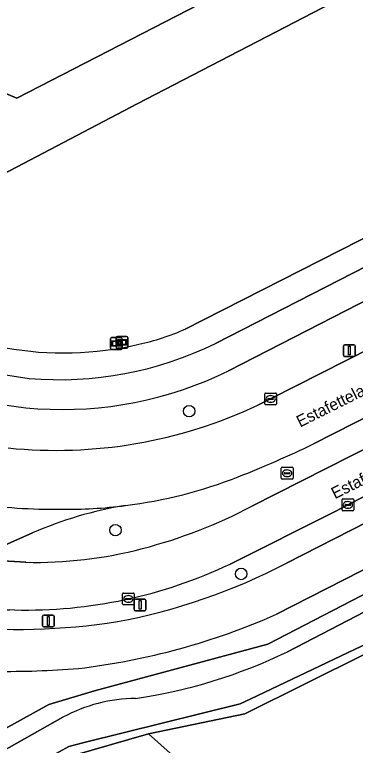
# Model space of a CAD drawing. Extents: x 158835 to 160077, y 386387 to 387778.
# Drawn here: x 159364.2 to 159393.2, y 386924.8 to 386987.1 of the extents above; entities that cross this region are included whole.
import ezdxf

# ---------------------------------------------------------------- set-up
doc = ezdxf.new("R2010")
doc.units = 0
for name, color, linetype in [('IMGEO_Berm_groen', 7, 'Continuous'), ('IMGEO_Boom', 7, 'Continuous'), ('IMGEO_Fietspad_gesloten', 7, 'Continuous'), ('IMGEO_Groenvoorziening', 7, 'Continuous'), ('IMGEO_Hek', 7, 'Continuous'), ('IMGEO_Kolk', 7, 'Continuous'), ('IMGEO_Lichtmast', 7, 'Continuous'), ('IMGEO_Loofbos', 7, 'Continuous'), ('IMGEO_Oever', 7, 'Continuous'), ('IMGEO_Openbare_ruimte_label', 7, 'Continuous'), ('IMGEO_OVBaan_gesloten', 7, 'Continuous'), ('IMGEO_Rijbaan_lokaal_gesloten', 7, 'Continuous'), ('IMGEO_Rioolput', 7, 'Continuous'), ('IMGEO_Verkeersbordpaal', 7, 'Continuous'), ('IMGEO_Verklikker', 7, 'Continuous'), ('IMGEO_Voetpad_open', 7, 'Continuous'), ('IMGEO_Waterloop', 7, 'Continuous')]:
    doc.layers.add(name, color=color, linetype=linetype)

msp = doc.modelspace()

# ---------------------------------------------------------------- linework, layer by layer
at = {"layer": 'IMGEO_Berm_groen'}
for points in [[(159428.091, 386980.187), (159382.431, 386956.783)], [(159384.924, 386953.836), (159386.022, 386954.376), (159398.908, 386960.912), (159415.355, 386969.266), (159429.86, 386976.665)], [(159432.141, 386972.104), (159389.664, 386950.538)], [(159384.418, 386945.227), (159433.268, 386969.982)], [(159434.931, 386966.882), (159434.868, 386966.85), (159404.602, 386951.444), (159392.61, 386945.349), (159391.514, 386944.789), (159382.575, 386940.303)], [(159387.376, 386940.385), (159435.723, 386965.048)], [(159365.727, 386942.951), (159362.552, 386941.571)], [(159362.672, 386940.602), (159365.133, 386940.451)]]:
    msp.add_lwpolyline(points, dxfattribs=at)
for centre, radius, start, end in [((159368.268, 386985.461), 31.985, 236.21061, 296.28288), ((159367.73, 386990.355), 40.364, 264.19141, 295.21233), ((159346.049, 387041.588), 100.958, 291.62283, 295.59561), ((159368.684, 386984.869), 39.889, 277.13541, 291.41905), ((159378.86, 386913.065), 32.645, 99.20291, 113.72196), ((159364.033, 386984.103), 43.897, 284.58939, 297.67073), ((159365.962, 386976.316), 35.874, 268.67508, 284.73992), ((159363.347, 386986.442), 51.949, 280.6721, 297.55231), ((159365.152, 386977.019), 40.64, 268.64408, 295.38662), ((159365.477, 386830.407), 105.991, 90.69551, 94.25258), ((159364.488, 386989.797), 55.062, 263.9691, 278.85816)]:
    msp.add_arc(centre, radius, start, end, dxfattribs=at)
at = {"layer": 'IMGEO_Boom'}
for centre in [(159379.078, 386953.336), (159372.785, 386943.191), (159383.508, 386939.459)]:
    msp.add_circle(centre, 0.489, dxfattribs=at)
at = {"layer": 'IMGEO_Fietspad_gesloten'}
for points in [[(159382.431, 386956.783), (159428.091, 386980.187), (159426.93, 386982.455), (159381.329, 386959.114)], [(159386.519, 386936.025), (159434.012, 386960.244), (159437.242, 386961.891), (159435.723, 386965.048), (159387.376, 386940.385)]]:
    msp.add_lwpolyline(points, dxfattribs=at)
for centre, radius, start, end in [((159369.367, 386988.541), 32.652, 237.26969, 263.08821), ((159368.04, 386986.036), 30.023, 265.02753, 296.27055), ((159368.268, 386985.461), 31.985, 236.21061, 296.28288), ((159363.347, 386986.442), 51.949, 280.6721, 297.55231), ((159362.835, 386989.408), 58.401, 276.67679, 293.92526), ((159364.488, 386989.797), 55.062, 263.9691, 278.85816), ((159363.587, 387005.299), 74.142, 269.19844, 274.6711)]:
    msp.add_arc(centre, radius, start, end, dxfattribs=at)
at = {"layer": 'IMGEO_Groenvoorziening'}
for points in [[(159492.942, 387127.124), (159492.925, 387127.157), (159491.486, 387129.957), (159491.48, 387129.969), (159454.996, 387200.96), (159454.739, 387200.828), (159488.799, 387134.444), (159483.442, 387131.694), (159530.436, 387039.892), (159523.22, 387036.235), (159466.963, 387007.729), (159456.775, 387027.573), (159364.368, 386980.011), (159361.936, 386981.03), (159330.518, 387042.115), (159326.469, 387040.039), (159326.519, 387039.941), (159327.376, 387040.359), (159360.9, 386972.353), (159374.649, 386979.517), (159454.32, 387020.797), (159462.644, 387004.65), (159523.508, 387035.675), (159536.529, 387042.312)], [(159483.442, 387131.694), (159453.236, 387116.189), (159453.617, 387115.493), (159447.106, 387112.128), (159446.642, 387112.841), (159431.844, 387105.183), (159432.221, 387104.371), (159425.755, 387101.094), (159425.292, 387101.79), (159413.519, 387095.807), (159415.826, 387091.297), (159418.055, 387087.12), (159407.481, 387081.56), (159395.596, 387075.514), (159389.288, 387072.22), (159387.317, 387071.247), (159330.518, 387042.115), (159361.936, 386981.03), (159364.368, 386980.011), (159456.775, 387027.573), (159466.963, 387007.729), (159523.22, 387036.235), (159530.436, 387039.892)], [(159426.473, 386939.935), (159425.959, 386940.91), (159436.694, 386946.325), (159437.191, 386945.362), (159454.436, 386954.123), (159458.282, 386956.083), (159457.971, 386956.706), (159457.606, 386957.3), (159457.189, 386957.858), (159456.724, 386958.376), (159456.214, 386958.851), (159455.963, 386959.046), (159444.244, 386952.199), (159437.136, 386954.065), (159414.812, 386942.941), (159383.823, 386927.545), (159375.595, 386925.829), (159379.553, 386922.312), (159383.008, 386919.242), (159383.953, 386918.403), (159408.648, 386930.908), (159408.146, 386931.898), (159418.899, 386937.349), (159419.39, 386936.348)]]:
    msp.add_lwpolyline(points, close=True, dxfattribs=at)
for points in [[(159332.172, 386900.099), (159339.03, 386909.825), (159341.407, 386912.222), (159344.595, 386914.968), (159353.41, 386920.761), (159367.113, 386928.324), (159370.995, 386929.506), (159385.785, 386933.475), (159425.412, 386953.997), (159434.793, 386958.672), (159434.012, 386960.244), (159386.519, 386936.025)], [(159359.061, 386915.103), (159379.553, 386922.312), (159375.595, 386925.829), (159369.094, 386923.958), (159353.377, 386915.342)]]:
    msp.add_lwpolyline(points, dxfattribs=at)
for centre, radius, start, end in [((159362.835, 386989.408), 58.401, 276.67679, 293.92526), ((159363.587, 387005.299), 74.142, 269.19844, 274.6711)]:
    msp.add_arc(centre, radius, start, end, dxfattribs=at)
at = {"layer": 'IMGEO_Hek'}
for points in [[(159374.649, 386979.517), (159454.32, 387020.797), (159462.644, 387004.65)], [(159374.649, 386979.517), (159360.9, 386972.353)]]:
    msp.add_lwpolyline(points, dxfattribs=at)
at = {"layer": 'IMGEO_Kolk'}
for p, q in [((159385.521, 386953.95), (159385.521, 386954.802)), ((159385.596, 386954.876), (159386.448, 386954.876)), ((159386.522, 386954.802), (159386.522, 386953.95)), ((159385.78, 386954.37), (159385.78, 386954.382)), ((159386.218, 386954.333), (159385.82, 386954.333)), ((159385.823, 386954.419), (159386.221, 386954.419)), ((159386.032, 386954.096), (159386.007, 386954.096)), ((159386.009, 386954.656), (159386.034, 386954.656)), ((159386.264, 386954.382), (159386.264, 386954.37)), ((159386.448, 386953.876), (159385.596, 386953.876)), ((159392.11, 386944.922), (159392.11, 386945.774)), ((159392.185, 386945.848), (159393.037, 386945.848)), ((159392.369, 386945.342), (159392.369, 386945.354)), ((159392.412, 386945.391), (159392.81, 386945.391)), ((159392.598, 386945.628), (159392.623, 386945.628)), ((159392.853, 386945.354), (159392.853, 386945.342)), ((159393.111, 386945.774), (159393.111, 386944.922)), ((159393.037, 386944.848), (159392.185, 386944.848)), ((159392.807, 386945.305), (159392.409, 386945.305)), ((159392.621, 386945.068), (159392.596, 386945.068)), ((159373.39, 386936.907), (159373.39, 386937.759)), ((159373.465, 386937.833), (159374.317, 386937.833)), ((159373.649, 386937.327), (159373.649, 386937.339)), ((159374.087, 386937.29), (159373.689, 386937.29)), ((159373.692, 386937.376), (159374.09, 386937.376)), ((159373.878, 386937.613), (159373.903, 386937.613)), ((159374.133, 386937.339), (159374.133, 386937.327)), ((159374.391, 386937.759), (159374.391, 386936.907)), ((159374.317, 386936.833), (159373.465, 386936.833)), ((159373.901, 386937.053), (159373.876, 386937.053))]:
    msp.add_line(p, q, dxfattribs=at)
for points in [[(159385.521, 386953.95), (159385.521, 386954.802)], [(159385.596, 386954.876), (159386.448, 386954.876)], [(159386.522, 386954.802), (159386.522, 386953.95)], [(159386.448, 386953.876), (159385.596, 386953.876)], [(159392.11, 386944.922), (159392.11, 386945.774)], [(159392.185, 386945.848), (159393.037, 386945.848)], [(159393.111, 386945.774), (159393.111, 386944.922)], [(159393.037, 386944.848), (159392.185, 386944.848)], [(159373.39, 386936.907), (159373.39, 386937.759)], [(159373.465, 386937.833), (159374.317, 386937.833)], [(159374.391, 386937.759), (159374.391, 386936.907)], [(159374.317, 386936.833), (159373.465, 386936.833)]]:
    msp.add_lwpolyline(points, dxfattribs=at)
for centre, radius, start, end in [((159385.598, 386954.8), 0.0765, 91.55205, 178.44795), ((159385.598, 386954.8), 0.0765, 91.55205, 178.44795), ((159386.446, 386954.8), 0.0765, 1.55205, 88.44795), ((159386.446, 386954.8), 0.0765, 1.55205, 88.44795), ((159385.82, 386954.379), 0.0403, 85.87752, 175.75265), ((159385.817, 386954.369), 0.0366, 178.93798, 274.71019), ((159386.221, 386954.376), 0.043, 264.86636, 352.45326), ((159386.225, 386954.381), 0.0386, 1.73085, 96.63898), ((159385.598, 386953.952), 0.0765, 181.55205, 268.44795), ((159385.598, 386953.952), 0.0765, 181.55205, 268.44795), ((159386.446, 386953.952), 0.0765, 271.55205, 358.44795), ((159386.446, 386953.952), 0.0765, 271.55205, 358.44795), ((159392.187, 386945.772), 0.0765, 91.55205, 178.44795), ((159392.187, 386945.772), 0.0765, 91.55205, 178.44795), ((159392.409, 386945.351), 0.0403, 85.87752, 175.75265), ((159392.814, 386945.353), 0.0386, 1.73085, 96.63898), ((159393.035, 386945.772), 0.0765, 1.55205, 88.44795), ((159393.035, 386945.772), 0.0765, 1.55205, 88.44795), ((159392.187, 386944.924), 0.0765, 181.55205, 268.44795), ((159392.187, 386944.924), 0.0765, 181.55205, 268.44795), ((159392.406, 386945.341), 0.0366, 178.93798, 274.71019), ((159392.81, 386945.348), 0.043, 264.86636, 352.45326), ((159393.035, 386944.924), 0.0765, 271.55205, 358.44795), ((159393.035, 386944.924), 0.0765, 271.55205, 358.44795), ((159373.467, 386937.757), 0.0765, 91.55205, 178.44795), ((159373.467, 386937.757), 0.0765, 91.55205, 178.44795), ((159373.689, 386937.336), 0.0403, 85.87752, 175.75265), ((159373.686, 386937.326), 0.0366, 178.93798, 274.71019), ((159374.09, 386937.333), 0.043, 264.86636, 352.45326), ((159374.094, 386937.338), 0.0386, 1.73085, 96.63898), ((159374.315, 386937.757), 0.0765, 1.55205, 88.44795), ((159374.315, 386937.757), 0.0765, 1.55205, 88.44795), ((159373.467, 386936.909), 0.0765, 181.55205, 268.44795), ((159373.467, 386936.909), 0.0765, 181.55205, 268.44795), ((159374.315, 386936.909), 0.0765, 271.55205, 358.44795), ((159374.315, 386936.909), 0.0765, 271.55205, 358.44795)]:
    msp.add_arc(centre, radius, start, end, dxfattribs=at)
for centre, major_axis, ratio, start_param, end_param in [((159386.008, 386954.376), (-0.387, 0.002), 0.722429, 4.712389, 7.853982), ((159386.033, 386954.376), (-0.39, 0.002), 0.717154, 1.570796, 4.712389), ((159392.597, 386945.348), (-0.387, 0.002), 0.722429, 4.712389, 7.853982), ((159392.622, 386945.348), (-0.39, 0.002), 0.717154, 1.570796, 4.712389), ((159373.877, 386937.333), (-0.387, 0.002), 0.722429, 4.712389, 7.853982), ((159373.902, 386937.333), (-0.39, 0.002), 0.717154, 1.570796, 4.712389)]:
    msp.add_ellipse(centre, major_axis=major_axis, ratio=ratio, start_param=start_param, end_param=end_param, dxfattribs=at)
at = {"layer": 'IMGEO_Lichtmast'}
for p, q in [((159392.229, 386958.096), (159392.229, 386958.896)), ((159392.229, 386958.896), (159392.229, 386958.096)), ((159392.329, 386958.996), (159393.119, 386958.996)), ((159393.119, 386958.996), (159392.329, 386958.996)), ((159393.219, 386958.896), (159393.219, 386958.096)), ((159393.219, 386958.096), (159393.219, 386958.896)), ((159393.119, 386957.996), (159392.329, 386957.996)), ((159392.329, 386957.996), (159393.119, 386957.996)), ((159374.497, 386937.322), (159375.287, 386937.322)), ((159375.287, 386937.322), (159374.497, 386937.322)), ((159374.397, 386936.422), (159374.397, 386937.222)), ((159374.397, 386937.222), (159374.397, 386936.422)), ((159375.387, 386937.222), (159375.387, 386936.422)), ((159375.387, 386936.422), (159375.387, 386937.222)), ((159375.287, 386936.322), (159374.497, 386936.322)), ((159374.497, 386936.322), (159375.287, 386936.322))]:
    msp.add_line(p, q, dxfattribs=at)
for points in [[(159392.649, 386958.871), (159392.799, 386958.871), (159392.799, 386958.121), (159392.649, 386958.121), (159392.649, 386958.871)], [(159374.817, 386937.197), (159374.967, 386937.197), (159374.967, 386936.447), (159374.817, 386936.447), (159374.817, 386937.197)]]:
    msp.add_lwpolyline(points, dxfattribs=at)
for centre, start, end in [((159392.329, 386958.896), 90, 180), ((159392.329, 386958.896), 90, 180), ((159393.119, 386958.896), 0, 90), ((159393.119, 386958.896), 360, 90), ((159392.329, 386958.096), 180, 270), ((159392.329, 386958.096), 180, 270), ((159393.119, 386958.096), 270, 0), ((159393.119, 386958.096), 270, 0), ((159374.497, 386937.222), 90, 180), ((159374.497, 386937.222), 90, 180), ((159375.287, 386937.222), 0, 90), ((159375.287, 386937.222), 360, 90), ((159374.497, 386936.422), 180, 270), ((159374.497, 386936.422), 180, 270), ((159375.287, 386936.422), 270, 0), ((159375.287, 386936.422), 270, 0)]:
    msp.add_arc(centre, 0.1, start, end, dxfattribs=at)
at = {"layer": 'IMGEO_Loofbos'}
for points in [[(159456.761, 387000), (159463.326, 387003.338), (159462.644, 387004.65), (159454.32, 387020.797), (159374.649, 386979.517), (159360.9, 386972.353), (159350.454, 386966.808), (159349.045, 386966.062)], [(159378.735, 386960.331), (159380.296, 386961.115), (159456.761, 387000)]]:
    msp.add_lwpolyline(points, dxfattribs=at)
for centre, radius, start, end in [((159368.364, 386986.234), 27.94, 236.37895, 283.25988), ((159371.066, 386977.126), 18.463, 281.58115, 294.54093)]:
    msp.add_arc(centre, radius, start, end, dxfattribs=at)
at = {"layer": 'IMGEO_Oever'}
for points in [[(159434.793, 386958.672), (159425.412, 386953.997), (159385.785, 386933.475), (159370.995, 386929.506), (159367.113, 386928.324), (159353.41, 386920.761), (159344.595, 386914.968), (159341.407, 386912.222), (159339.03, 386909.825), (159332.172, 386900.099)], [(159387.446, 386932.829), (159408.678, 386943.835), (159434.099, 386957.264), (159434.364, 386956.666), (159435.524, 386957.108), (159436.161, 386955.67), (159435.349, 386955.342), (159435.657, 386954.536), (159419.477, 386946.302), (159407.957, 386940.347), (159397.3, 386934.967), (159384.343, 386928.827), (159383.419, 386928.396), (159370.134, 386925.09), (159368.82, 386924.762), (159364.692, 386922.482), (159349.703, 386914.207), (159347.074, 386912.4), (159345.062, 386910.614), (159342.31, 386907.883), (159334.364, 386897.636), (159332.269, 386896.343), (159329.559, 386895.829), (159329.252, 386895.292)], [(159353.377, 386915.342), (159369.094, 386923.958), (159375.595, 386925.829), (159383.823, 386927.545), (159414.812, 386942.941), (159437.136, 386954.065)], [(159345.639, 386914.472), (159368.309, 386927.244)]]:
    msp.add_lwpolyline(points, dxfattribs=at)
for centre, radius, start, end in [((159368.063, 386972.771), 44.396, 278.34924, 295.88609), ((159374.618, 386915.617), 13.229, 90.46831, 118.48513)]:
    msp.add_arc(centre, radius, start, end, dxfattribs=at)
at = {"layer": 'IMGEO_OVBaan_gesloten'}
msp.add_lwpolyline([(159362.552, 386941.571), (159365.727, 386942.951)], dxfattribs=at)
for centre, radius, start, end in [((159367.396, 386987.407), 42.434, 260.94117, 270.9854), ((159378.86, 386913.065), 32.645, 99.20291, 113.72196), ((159368.749, 386983.078), 38.104, 269.06336, 277.37343)]:
    msp.add_arc(centre, radius, start, end, dxfattribs=at)
at = {"layer": 'IMGEO_Rijbaan_lokaal_gesloten'}
for points in [[(159432.141, 386972.104), (159429.86, 386976.665), (159415.355, 386969.266), (159398.908, 386960.912), (159386.022, 386954.376), (159384.924, 386953.836)], [(159389.664, 386950.538), (159432.141, 386972.104)], [(159434.868, 386966.85), (159433.268, 386969.982), (159384.418, 386945.227)], [(159382.575, 386940.303), (159391.514, 386944.789), (159392.61, 386945.349), (159404.602, 386951.444), (159434.868, 386966.85)], [(159365.133, 386940.451), (159362.672, 386940.602)]]:
    msp.add_lwpolyline(points, dxfattribs=at)
for centre, radius, start, end in [((159367.73, 386990.355), 40.364, 264.19141, 295.21233), ((159346.049, 387041.588), 100.958, 291.62283, 295.59561), ((159368.684, 386984.869), 39.889, 277.13541, 291.41905), ((159367.396, 386987.407), 42.434, 260.94117, 270.9854), ((159368.749, 386983.078), 38.104, 269.06336, 277.37343), ((159364.033, 386984.103), 43.897, 284.58939, 297.67073), ((159365.962, 386976.316), 35.874, 268.67508, 284.73992), ((159365.152, 386977.019), 40.64, 268.64408, 295.38662), ((159367.081, 386993.796), 57.479, 255.29476, 267.11725), ((159367.081, 386993.796), 57.479, 255.29476, 267.11725), ((159365.477, 386830.407), 105.991, 90.69551, 94.25258)]:
    msp.add_arc(centre, radius, start, end, dxfattribs=at)
at = {"layer": 'IMGEO_Rioolput'}
for p, q in [((159386.927, 386947.621), (159386.927, 386948.473)), ((159387.002, 386948.547), (159387.854, 386948.547)), ((159387.928, 386948.473), (159387.928, 386947.621)), ((159387.186, 386948.041), (159387.186, 386948.053)), ((159387.624, 386948.004), (159387.226, 386948.004)), ((159387.229, 386948.09), (159387.627, 386948.09)), ((159387.415, 386948.327), (159387.44, 386948.327)), ((159387.67, 386948.053), (159387.67, 386948.041)), ((159387.854, 386947.547), (159387.002, 386947.547)), ((159387.438, 386947.767), (159387.413, 386947.767))]:
    msp.add_line(p, q, dxfattribs=at)
for points in [[(159386.927, 386947.621), (159386.927, 386948.473)], [(159387.002, 386948.547), (159387.854, 386948.547)], [(159387.928, 386948.473), (159387.928, 386947.621)], [(159387.854, 386947.547), (159387.002, 386947.547)]]:
    msp.add_lwpolyline(points, dxfattribs=at)
for centre, radius, start, end in [((159387.004, 386948.471), 0.0765, 91.55205, 178.44795), ((159387.004, 386948.471), 0.0765, 91.55205, 178.44795), ((159387.852, 386948.471), 0.0765, 1.55205, 88.44795), ((159387.852, 386948.471), 0.0765, 1.55205, 88.44795), ((159387.226, 386948.05), 0.0403, 85.87752, 175.75265), ((159387.223, 386948.04), 0.0366, 178.93798, 274.71019), ((159387.627, 386948.047), 0.043, 264.86636, 352.45326), ((159387.631, 386948.052), 0.0386, 1.73085, 96.63898), ((159387.004, 386947.623), 0.0765, 181.55205, 268.44795), ((159387.004, 386947.623), 0.0765, 181.55205, 268.44795), ((159387.852, 386947.623), 0.0765, 271.55205, 358.44795), ((159387.852, 386947.623), 0.0765, 271.55205, 358.44795)]:
    msp.add_arc(centre, radius, start, end, dxfattribs=at)
for centre, major_axis, ratio, start_param, end_param in [((159387.414, 386948.047), (-0.387, 0.002), 0.722429, 4.712389, 7.853982), ((159387.439, 386948.047), (-0.39, 0.002), 0.717154, 1.570796, 4.712389)]:
    msp.add_ellipse(centre, major_axis=major_axis, ratio=ratio, start_param=start_param, end_param=end_param, dxfattribs=at)
at = {"layer": 'IMGEO_Verkeersbordpaal'}
for p, q in [((159366.571, 386935.05), (159366.571, 386935.85)), ((159366.571, 386935.85), (159366.571, 386935.05)), ((159366.671, 386935.95), (159367.461, 386935.95)), ((159367.461, 386935.95), (159366.671, 386935.95)), ((159367.561, 386935.85), (159367.561, 386935.05)), ((159367.561, 386935.05), (159367.561, 386935.85)), ((159367.461, 386934.95), (159366.671, 386934.95)), ((159366.671, 386934.95), (159367.461, 386934.95))]:
    msp.add_line(p, q, dxfattribs=at)
msp.add_lwpolyline([(159366.991, 386935.825), (159367.141, 386935.825), (159367.141, 386935.075), (159366.991, 386935.075), (159366.991, 386935.825)], dxfattribs=at)
for centre, start, end in [((159366.671, 386935.85), 90, 180), ((159366.671, 386935.85), 90, 180), ((159367.461, 386935.85), 0, 90), ((159367.461, 386935.85), 360, 90), ((159366.671, 386935.05), 180, 270), ((159366.671, 386935.05), 180, 270), ((159367.461, 386935.05), 270, 0), ((159367.461, 386935.05), 270, 0)]:
    msp.add_arc(centre, 0.1, start, end, dxfattribs=at)
at = {"layer": 'IMGEO_Verklikker'}
for p, q in [((159372.954, 386959.7), (159373.744, 386959.7)), ((159373.744, 386959.7), (159372.954, 386959.7)), ((159372.379, 386958.698), (159372.379, 386959.498)), ((159372.379, 386959.498), (159372.379, 386958.698)), ((159372.479, 386959.598), (159373.269, 386959.598)), ((159373.269, 386959.598), (159372.479, 386959.598)), ((159372.854, 386958.8), (159372.854, 386959.6)), ((159372.854, 386959.6), (159372.854, 386958.8)), ((159373.369, 386959.498), (159373.369, 386958.698)), ((159373.369, 386958.698), (159373.369, 386959.498)), ((159373.844, 386959.6), (159373.844, 386958.8)), ((159373.844, 386958.8), (159373.844, 386959.6)), ((159373.269, 386958.598), (159372.479, 386958.598)), ((159372.479, 386958.598), (159373.269, 386958.598)), ((159373.744, 386958.7), (159372.954, 386958.7)), ((159372.954, 386958.7), (159373.744, 386958.7))]:
    msp.add_line(p, q, dxfattribs=at)
for points in [[(159372.48, 386959.33), (159373.268, 386959.33), (159373.268, 386958.866), (159372.48, 386958.866), (159372.48, 386959.33)], [(159372.545, 386959.265), (159372.545, 386958.931), (159373.203, 386958.931), (159373.203, 386959.265), (159372.545, 386959.265)], [(159372.955, 386959.432), (159373.743, 386959.432), (159373.743, 386958.968), (159372.955, 386958.968), (159372.955, 386959.432)], [(159373.02, 386959.367), (159373.02, 386959.033), (159373.678, 386959.033), (159373.678, 386959.367), (159373.02, 386959.367)]]:
    msp.add_lwpolyline(points, dxfattribs=at)
for centre, start, end in [((159372.954, 386959.6), 90, 180), ((159372.954, 386959.6), 90, 180), ((159373.744, 386959.6), 0, 90), ((159373.744, 386959.6), 360, 90), ((159372.479, 386959.498), 90, 180), ((159372.479, 386959.498), 90, 180), ((159373.269, 386959.498), 0, 90), ((159373.269, 386959.498), 360, 90), ((159372.479, 386958.698), 180, 270), ((159372.479, 386958.698), 180, 270), ((159372.954, 386958.8), 180, 270), ((159372.954, 386958.8), 180, 270), ((159373.269, 386958.698), 270, 0), ((159373.269, 386958.698), 270, 0), ((159373.744, 386958.8), 270, 0), ((159373.744, 386958.8), 270, 0)]:
    msp.add_arc(centre, 0.1, start, end, dxfattribs=at)
at = {"layer": 'IMGEO_Voetpad_open'}
for points in [[(159544.906, 387044.825), (159524.214, 387034.303), (159500, 387021.989), (159463.326, 387003.338), (159456.761, 387000), (159380.296, 386961.115), (159378.735, 386960.331)], [(159381.329, 386959.114), (159426.93, 386982.455), (159427.151, 386982.568), (159457.994, 386998.14), (159461.651, 387000), (159500, 387019.508)]]:
    msp.add_lwpolyline(points, dxfattribs=at)
for centre, radius, start, end in [((159368.364, 386986.234), 27.94, 236.37895, 283.25988), ((159369.367, 386988.541), 32.652, 237.26969, 263.08821), ((159371.066, 386977.126), 18.463, 281.58115, 294.54093), ((159368.04, 386986.036), 30.023, 265.02753, 296.27055)]:
    msp.add_arc(centre, radius, start, end, dxfattribs=at)
at = {"layer": 'IMGEO_Waterloop'}
for points in [[(159383.419, 386928.396), (159384.343, 386928.827), (159397.3, 386934.967), (159407.957, 386940.347), (159419.477, 386946.302), (159435.657, 386954.536), (159435.349, 386955.342), (159436.161, 386955.67), (159435.524, 386957.108), (159434.364, 386956.666), (159434.099, 386957.264), (159408.678, 386943.835), (159387.446, 386932.829)], [(159325.962, 386900.454), (159324.335, 386898.427), (159327.18, 386896.628), (159327.142, 386895.909), (159327.72, 386895.74), (159328.728, 386895.445), (159329.252, 386895.292), (159329.559, 386895.829), (159332.269, 386896.343), (159334.364, 386897.636), (159342.31, 386907.883), (159345.062, 386910.614), (159347.074, 386912.4), (159349.703, 386914.207), (159364.692, 386922.482), (159368.82, 386924.762), (159370.134, 386925.09), (159383.419, 386928.396)], [(159368.309, 386927.244), (159345.639, 386914.472)]]:
    msp.add_lwpolyline(points, dxfattribs=at)
for centre, radius, start, end in [((159368.063, 386972.771), 44.396, 278.34924, 295.88609), ((159374.618, 386915.617), 13.229, 90.46831, 118.48513)]:
    msp.add_arc(centre, radius, start, end, dxfattribs=at)

# ---------------------------------------------------------------- texts
at = {"layer": 'IMGEO_Openbare_ruimte_label'}
for p in [(159388.531, 386951.937), (159391.502, 386945.818)]:
    msp.add_text('Estafettelaan', height=1, rotation=26.43687, dxfattribs=at).set_placement(p)

doc.saveas('drawing.dxf')
